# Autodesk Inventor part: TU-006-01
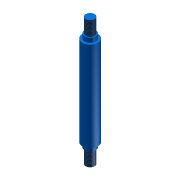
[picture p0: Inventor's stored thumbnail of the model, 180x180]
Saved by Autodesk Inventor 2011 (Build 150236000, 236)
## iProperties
Created: 2002-07
Part Number: TU-006-01
Material: Stainless Steel
Description: Piston Rod - 35 mm stroke
Document SubType Name: Modeling
Designer: PN
Mass: 144.065 g
Surface Area: 58.412 cm^2
Volume: 17.8299 cm^3
Density: 8.08 g/cm^3
Author: PN
Stroke_Length: 35.000 mm
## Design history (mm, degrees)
derived "Piston Rod.ipt" dims "d11" = 14, "d15" = 115, "d16" = 8, "d32" = 13, "d33" = 4, "d36" = 81, "d38" = 4, "Stroke_Length" = 35
body "Solid1"
feature "Solid1::Piston Rod.ipt" dims "d11" = 14, "d15" = 115, "d16" = 8, "d17" = 10, "d32" = 13, "d33" = 4, "d36" = 81, "d38" = 4, "Stroke_Length" = 35, "ScaleForDerivedMember" = 10
tag "TaggingFeature1"
